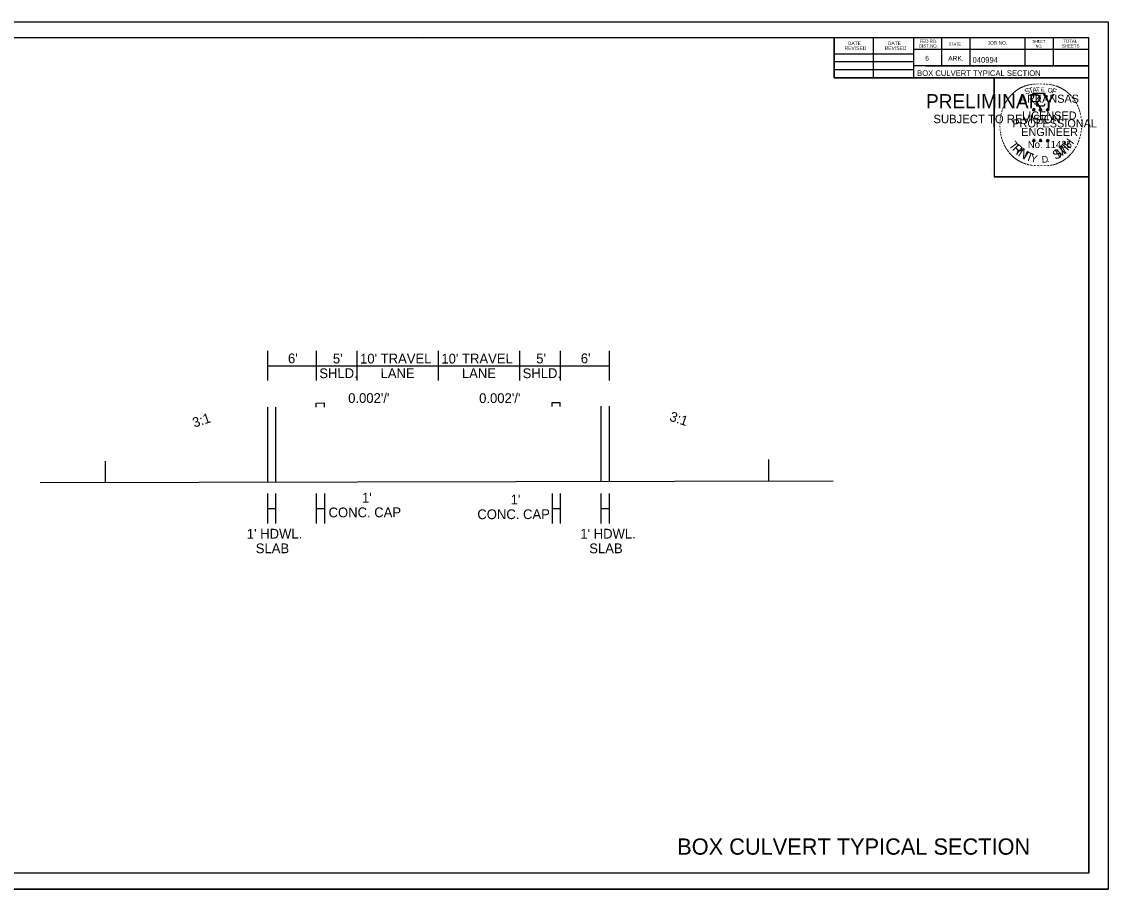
# Model space of a CAD drawing. Extents: x 1381471 to 1382703, y 370300 to 371487.
# Drawn here: x 1382383.6 to 1382517.2, y 370748.7 to 370855.4 of the extents above; entities that cross this region are included whole.
import ezdxf

# ---------------------------------------------------------------- set-up
doc = ezdxf.new("R2010")
doc.units = 0
for name, color, linetype in [('Default', 7, 'Continuous'), ('Level 15', 7, 'Continuous'), ('Level 16', 7, 'Continuous'), ('Level 21', 7, 'Continuous'), ('Level 26', 7, 'Continuous'), ('Level 39', 7, 'Continuous'), ('Level 6', 7, 'Continuous'), ('Level 8', 7, 'Continuous'), ('Level 9', 7, 'Continuous')]:
    doc.layers.add(name, color=color, linetype=linetype)

msp = doc.modelspace()

# ---------------------------------------------------------------- linework, layer by layer
at = {"layer": 'Default'}
for p, q in [((1382413.84, 370808.01), (1382413.84, 370798.75)), ((1382414.84, 370808.01), (1382414.84, 370798.75)), ((1382454.84, 370808.11), (1382454.84, 370798.85)), ((1382455.84, 370808.11), (1382455.84, 370798.85)), ((1382393.92, 370798.7), (1382393.92, 370801.37)), ((1382475.47, 370798.9), (1382475.47, 370801.56))]:
    msp.add_line(p, q, dxfattribs=at)
at = {"layer": 'Level 16'}
msp.add_line((1382483.39, 370798.91), (1382385.89, 370798.68), dxfattribs=at)
at = {"layer": 'Level 26'}
for p, q in [((1382350.55, 370855.4), (1382517.22, 370855.4)), ((1382502.86, 370837.28), (1382502.86, 370837.28)), ((1382350.55, 370748.73), (1382517.22, 370748.73))]:
    msp.add_line(p, q, dxfattribs=at)
for points in [[(1382350.55, 370855.4), (1382517.22, 370855.4), (1382517.22, 370748.73), (1382350.55, 370748.73)], [(1382473.71, 370853.45), (1382483.52, 370853.45), (1382483.52, 370848.51), (1382491.58, 370848.51), (1382503.17, 370848.51), (1382503.17, 370836.34), (1382514.84, 370836.34), (1382514.84, 370750.72), (1382356.75, 370750.72), (1382356.75, 370853.45)], [(1382503.17, 370848.51), (1382514.78, 370848.51), (1382514.84, 370836.34), (1382503.24, 370836.34)]]:
    msp.add_lwpolyline(points, close=True, dxfattribs=at)
at = {"layer": 'Level 39'}
for p, q in [((1382419.84, 370808.01), (1382419.84, 370808.51)), ((1382420.84, 370808.02), (1382420.84, 370808.52)), ((1382448.84, 370808.08), (1382448.84, 370808.58)), ((1382449.84, 370808.08), (1382449.84, 370808.58))]:
    msp.add_line(p, q, dxfattribs=at)
at = {"layer": 'Level 6'}
for p, q in [((1382356.75, 370853.45), (1382514.84, 370853.45)), ((1382433.01, 370853.32), (1382433.01, 370853.32)), ((1382433.01, 370853.32), (1382433.01, 370853.32)), ((1382483.52, 370848.51), (1382483.52, 370853.45)), ((1382488.36, 370848.51), (1382488.36, 370853.45)), ((1382493.29, 370853.45), (1382493.29, 370848.51)), ((1382496.71, 370853.45), (1382496.71, 370849.98)), ((1382500.18, 370853.45), (1382500.18, 370849.98)), ((1382506.97, 370853.45), (1382506.97, 370849.98)), ((1382510.44, 370853.45), (1382510.44, 370849.98)), ((1382514.84, 370750.72), (1382514.84, 370853.45)), ((1382514.84, 370851.98), (1382493.29, 370851.98)), ((1382514.84, 370851.99), (1382514.84, 370851.99)), ((1382483.52, 370851.44), (1382493.29, 370851.44)), ((1382483.52, 370850.51), (1382493.29, 370850.51)), ((1382483.52, 370849.54), (1382493.29, 370849.54)), ((1382514.84, 370849.98), (1382493.29, 370849.98)), ((1382494.77, 370849.98), (1382514.84, 370849.98)), ((1382514.84, 370848.51), (1382483.52, 370848.51)), ((1382413.84, 370814.91), (1382413.84, 370811.27)), ((1382419.84, 370814.91), (1382419.84, 370811.27)), ((1382424.84, 370814.91), (1382424.84, 370811.27)), ((1382434.84, 370814.91), (1382434.84, 370811.27)), ((1382444.84, 370814.91), (1382444.84, 370811.27)), ((1382449.84, 370814.91), (1382449.84, 370811.27)), ((1382455.84, 370814.91), (1382455.84, 370811.27)), ((1382413.84, 370813.09), (1382455.84, 370813.09)), ((1382419.84, 370808.51), (1382420.84, 370808.52)), ((1382448.84, 370808.58), (1382449.84, 370808.58)), ((1382413.84, 370797.37), (1382413.84, 370793.72)), ((1382414.84, 370797.37), (1382414.84, 370793.72)), ((1382419.84, 370797.37), (1382419.84, 370793.72)), ((1382420.84, 370797.37), (1382420.84, 370793.72)), ((1382448.84, 370797.37), (1382448.84, 370793.72)), ((1382449.84, 370797.37), (1382449.84, 370793.72)), ((1382454.84, 370797.37), (1382454.84, 370793.72)), ((1382455.84, 370797.37), (1382455.84, 370793.72)), ((1382413.84, 370795.54), (1382414.84, 370795.54)), ((1382419.84, 370795.54), (1382420.84, 370795.54)), ((1382448.84, 370795.54), (1382449.84, 370795.54)), ((1382454.84, 370795.54), (1382455.84, 370795.54)), ((1382514.84, 370750.72), (1382356.75, 370750.72))]:
    msp.add_line(p, q, dxfattribs=at)
at = {"layer": 'Level 8'}
for p, q in [((1382507.88, 370844.64), (1382508.06, 370844.58)), ((1382507.88, 370844.64), (1382508.01, 370844.61)), ((1382507.88, 370844.64), (1382508, 370844.57)), ((1382507.95, 370844.43), (1382508.06, 370844.58)), ((1382507.95, 370844.43), (1382508.01, 370844.55)), ((1382507.95, 370844.43), (1382508.06, 370844.54)), ((1382508.06, 370844.76), (1382508.04, 370844.64)), ((1382508.06, 370844.58), (1382508.06, 370844.76)), ((1382508.06, 370844.76), (1382508.08, 370844.64)), ((1382508.23, 370844.64), (1382508.06, 370844.58)), ((1382508.16, 370844.43), (1382508.06, 370844.58)), ((1382508.16, 370844.43), (1382508.06, 370844.54)), ((1382508.23, 370844.64), (1382508.09, 370844.61)), ((1382508.16, 370844.43), (1382508.09, 370844.58)), ((1382508.23, 370844.64), (1382508.13, 370844.58)), ((1382508.72, 370844.64), (1382508.89, 370844.58)), ((1382508.72, 370844.64), (1382508.84, 370844.61)), ((1382508.72, 370844.64), (1382508.84, 370844.57)), ((1382508.78, 370844.43), (1382508.89, 370844.58)), ((1382508.78, 370844.43), (1382508.85, 370844.55)), ((1382508.78, 370844.43), (1382508.89, 370844.54)), ((1382508.89, 370844.76), (1382508.87, 370844.64)), ((1382508.89, 370844.58), (1382508.89, 370844.76)), ((1382508.89, 370844.76), (1382508.92, 370844.64)), ((1382509.06, 370844.64), (1382508.89, 370844.58)), ((1382509, 370844.43), (1382508.89, 370844.58)), ((1382509, 370844.43), (1382508.89, 370844.54)), ((1382509.06, 370844.64), (1382508.92, 370844.61)), ((1382509, 370844.43), (1382508.93, 370844.58)), ((1382509.06, 370844.64), (1382508.96, 370844.58)), ((1382509.6, 370844.63), (1382509.77, 370844.57)), ((1382509.6, 370844.63), (1382509.73, 370844.61)), ((1382509.6, 370844.63), (1382509.72, 370844.57)), ((1382509.67, 370844.43), (1382509.77, 370844.57)), ((1382509.67, 370844.43), (1382509.73, 370844.55)), ((1382509.67, 370844.43), (1382509.77, 370844.53)), ((1382509.77, 370844.76), (1382509.75, 370844.63)), ((1382509.77, 370844.57), (1382509.77, 370844.76)), ((1382509.77, 370844.76), (1382509.8, 370844.63)), ((1382509.95, 370844.63), (1382509.77, 370844.57)), ((1382509.88, 370844.43), (1382509.77, 370844.57)), ((1382509.88, 370844.43), (1382509.77, 370844.53)), ((1382509.95, 370844.63), (1382509.8, 370844.6)), ((1382509.88, 370844.43), (1382509.81, 370844.57)), ((1382509.95, 370844.63), (1382509.84, 370844.58)), ((1382507.88, 370840.85), (1382508.05, 370840.79)), ((1382507.88, 370840.85), (1382508.01, 370840.83)), ((1382507.88, 370840.85), (1382508, 370840.79)), ((1382507.95, 370840.64), (1382508.05, 370840.79)), ((1382507.95, 370840.64), (1382508.01, 370840.77)), ((1382507.95, 370840.64), (1382508.05, 370840.75)), ((1382508.05, 370840.98), (1382508.03, 370840.85)), ((1382508.05, 370840.79), (1382508.05, 370840.98)), ((1382508.05, 370840.98), (1382508.08, 370840.85)), ((1382508.23, 370840.85), (1382508.05, 370840.79)), ((1382508.16, 370840.64), (1382508.05, 370840.79)), ((1382508.16, 370840.64), (1382508.05, 370840.75)), ((1382508.23, 370840.85), (1382508.08, 370840.82)), ((1382508.16, 370840.64), (1382508.09, 370840.79)), ((1382508.23, 370840.85), (1382508.13, 370840.8)), ((1382508.71, 370840.85), (1382508.89, 370840.79)), ((1382508.71, 370840.85), (1382508.84, 370840.83)), ((1382508.71, 370840.85), (1382508.83, 370840.79)), ((1382508.78, 370840.64), (1382508.89, 370840.79)), ((1382508.78, 370840.64), (1382508.84, 370840.77)), ((1382508.78, 370840.64), (1382508.89, 370840.75)), ((1382508.89, 370840.98), (1382508.87, 370840.85)), ((1382508.89, 370840.79), (1382508.89, 370840.98)), ((1382508.89, 370840.98), (1382508.91, 370840.85)), ((1382509.06, 370840.85), (1382508.89, 370840.79)), ((1382509, 370840.64), (1382508.89, 370840.79)), ((1382509, 370840.64), (1382508.89, 370840.75)), ((1382509.06, 370840.85), (1382508.92, 370840.82)), ((1382509, 370840.64), (1382508.93, 370840.79)), ((1382509.06, 370840.85), (1382508.96, 370840.8)), ((1382509.6, 370840.84), (1382509.77, 370840.79)), ((1382509.6, 370840.84), (1382509.72, 370840.82)), ((1382509.6, 370840.84), (1382509.72, 370840.78)), ((1382509.66, 370840.64), (1382509.77, 370840.79)), ((1382509.66, 370840.64), (1382509.73, 370840.76)), ((1382509.66, 370840.64), (1382509.77, 370840.75)), ((1382509.77, 370840.97), (1382509.75, 370840.84)), ((1382509.77, 370840.79), (1382509.77, 370840.97)), ((1382509.77, 370840.97), (1382509.8, 370840.85)), ((1382509.95, 370840.84), (1382509.77, 370840.79)), ((1382509.88, 370840.64), (1382509.77, 370840.79)), ((1382509.88, 370840.64), (1382509.77, 370840.75)), ((1382509.95, 370840.84), (1382509.8, 370840.82)), ((1382509.88, 370840.64), (1382509.81, 370840.79)), ((1382509.95, 370840.84), (1382509.84, 370840.79))]:
    msp.add_line(p, q, dxfattribs=at)
for points in [[(1382507.9, 370846.57), (1382508.04, 370846.16)], [(1382509.66, 370846.11), (1382509.73, 370846.26), (1382509.39, 370846.24), (1382509.46, 370846.57), (1382507.9, 370846.57)], [(1382508.15, 370845.36), (1382508.15, 370845.32), (1382508.43, 370845.31), (1382508.4, 370845.07), (1382509.34, 370845.07), (1382509.44, 370845.34)], [(1382508.06, 370844.76), (1382508.16, 370844.43), (1382507.88, 370844.64), (1382508.23, 370844.64), (1382507.95, 370844.43), (1382508.06, 370844.76)], [(1382508.89, 370844.76), (1382509, 370844.43), (1382508.72, 370844.64), (1382509.06, 370844.64), (1382508.78, 370844.43), (1382508.89, 370844.76)], [(1382509.77, 370844.76), (1382509.88, 370844.43), (1382509.6, 370844.63), (1382509.95, 370844.63), (1382509.67, 370844.43), (1382509.77, 370844.76)], [(1382508.05, 370840.98), (1382508.16, 370840.64), (1382507.88, 370840.85), (1382508.23, 370840.85), (1382507.95, 370840.64), (1382508.05, 370840.98)], [(1382508.89, 370840.98), (1382509, 370840.64), (1382508.71, 370840.85), (1382509.06, 370840.85), (1382508.78, 370840.64), (1382508.89, 370840.98)], [(1382509.77, 370840.97), (1382509.88, 370840.64), (1382509.6, 370840.84), (1382509.95, 370840.84), (1382509.66, 370840.64), (1382509.77, 370840.97)]]:
    msp.add_lwpolyline(points, dxfattribs=at)
for centre, radius in [((1382508.06, 370844.58), 0.0861), ((1382508.06, 370844.58), 0.0723), ((1382508.06, 370844.58), 0.0579), ((1382508.06, 370844.58), 0.0495), ((1382508.06, 370844.58), 0.0374), ((1382508.06, 370844.58), 0.0248), ((1382508.06, 370844.58), 0.0148), ((1382508.89, 370844.58), 0.0861), ((1382508.89, 370844.58), 0.0723), ((1382508.89, 370844.58), 0.0579), ((1382508.89, 370844.58), 0.0495), ((1382508.89, 370844.58), 0.0374), ((1382508.89, 370844.58), 0.0248), ((1382508.89, 370844.58), 0.0148), ((1382509.77, 370844.57), 0.0861), ((1382509.77, 370844.57), 0.0723), ((1382509.77, 370844.57), 0.0579), ((1382509.77, 370844.57), 0.0495), ((1382509.77, 370844.57), 0.0374), ((1382509.77, 370844.57), 0.0248), ((1382509.77, 370844.57), 0.0148), ((1382508.05, 370840.79), 0.0861), ((1382508.05, 370840.79), 0.0723), ((1382508.05, 370840.79), 0.0579), ((1382508.05, 370840.79), 0.0495), ((1382508.05, 370840.79), 0.0374), ((1382508.05, 370840.79), 0.0248), ((1382508.05, 370840.79), 0.0148), ((1382508.89, 370840.79), 0.0861), ((1382508.89, 370840.79), 0.0723), ((1382508.89, 370840.79), 0.0579), ((1382508.89, 370840.79), 0.0495), ((1382508.89, 370840.79), 0.0374), ((1382508.89, 370840.79), 0.0248), ((1382508.89, 370840.79), 0.0148), ((1382509.77, 370840.79), 0.0861), ((1382509.77, 370840.79), 0.0723), ((1382509.77, 370840.79), 0.0579), ((1382509.77, 370840.79), 0.0495), ((1382509.77, 370840.79), 0.0374), ((1382509.77, 370840.79), 0.0248), ((1382509.77, 370840.79), 0.0148)]:
    msp.add_circle(centre, radius, dxfattribs=at)

# ---------------------------------------------------------------- texts
at = {"layer": 'Level 15'}
msp.add_text('BOX CULVERT TYPICAL SECTION', height=2, dxfattribs=at).set_placement((1382464.22, 370752.98))
at = {"layer": 'Level 21'}
for s, rotation, p in [("6'", 0.1364, (1382416.37, 370813.4)), ("5'", 0.1364, (1382421.89, 370813.38)), ("10' TRAVEL ", 0.1364, (1382425.23, 370813.37)), ("10' TRAVEL ", 0.1364, (1382435.23, 370813.37)), ("5'", 0.1364, (1382446.89, 370813.38)), ("6'", 0.1364, (1382452.37, 370813.4)), ('SHLD.', 0.1364, (1382420.22, 370811.57)), ('LANE', 0.1364, (1382427.75, 370811.57)), ('LANE', 0.1364, (1382437.75, 370811.57)), ('SHLD.', 0.1364, (1382445.22, 370811.57)), ("0.002'/'", 0.1364, (1382423.77, 370808.52)), ("0.002'/'", 0.1365, (1382439.87, 370808.51)), ('3:1', 18.4349, (1382404.86, 370805.48)), ('3:1', 341.5651, (1382463.18, 370806.37)), ("1'", 0.1364, (1382425.46, 370796.27)), ("1'", 0.1364, (1382443.75, 370796.04)), ('CONC. CAP', 0.1364, (1382421.36, 370794.46)), ('CONC. CAP', 0.1364, (1382439.65, 370794.23)), ("1' HDWL.", 0.1364, (1382411.31, 370791.84)), ("1' HDWL.", 0.1364, (1382452.31, 370791.84)), ('SLAB', 0.1364, (1382412.41, 370790.04)), ('SLAB', 0.1364, (1382453.41, 370790.04))]:
    msp.add_text(s, height=1.2, rotation=rotation, dxfattribs=at).set_placement(p)
at = {"layer": 'Level 6'}
for s, height, p in [('REVISED', 0.44, (1382484.8, 370851.93)), ('DATE', 0.44, (1382485.19, 370852.52)), ('REVISED', 0.44, (1382489.73, 370851.93)), ('DATE', 0.44, (1382490.12, 370852.52)), ('DIST.NO.', 0.391, (1382493.93, 370852.22)), ('FED.RD.', 0.391, (1382494.03, 370852.81)), ('STATE', 0.342, (1382497.59, 370852.47)), ('JOB NO.', 0.44, (1382502.38, 370852.57)), ('SHEET', 0.342, (1382507.9, 370852.81)), ('NO.', 0.342, (1382508.29, 370852.22)), ('SHEETS', 0.391, (1382511.52, 370852.22)), ('TOTAL', 0.391, (1382511.66, 370852.81)), ('6', 0.586, (1382494.71, 370850.61)), ('ARK.', 0.586, (1382497.54, 370850.61)), ('040994', 0.7, (1382500.53, 370850.35)), ('BOX CULVERT TYPICAL SECTION', 0.7, (1382493.72, 370848.72))]:
    msp.add_text(s, height=height, rotation=360, dxfattribs=at).set_placement(p)
at = {"layer": 'Level 8'}
for s, height, rotation, p in [('-', 1.18, 42.9622, (1382505.6, 370846.06)), ('-', 1.19, 38.9507, (1382505.82, 370846.27)), ('-', 1.2, 36.2317, (1382506.05, 370846.46)), ('-', 1.2, 34.0636, (1382506.34, 370846.66)), ('-', 1.18, 28.7918, (1382506.64, 370846.84)), ('-', 1.15, 24.3072, (1382506.96, 370847)), ('S', 0.696, 21.594, (1382507.08, 370846.41)), ('-', 1.08, 19.1761, (1382507.28, 370847.14)), ('T', 0.645, 16.4036, (1382507.54, 370846.58)), ('-', 0.982, 13.6302, (1382507.65, 370847.26)), ('A', 0.585, 11.2132, (1382507.95, 370846.7)), ('-', 0.917, 10.2193, (1382507.99, 370847.34)), ('T', 0.529, 6.0228, (1382508.37, 370846.79)), ('-', 0.844, 5.8968, (1382508.35, 370847.39)), ('-', 0.8, 0.1862, (1382508.74, 370847.43)), ('E', 0.501, 0.8323, (1382508.93, 370846.84)), ('-', 0.807, 357.743, (1382509.1, 370847.42)), ('-', 0.874, 352.1617, (1382509.47, 370847.4)), ('O', 0.565, 350.4515, (1382509.73, 370846.74)), ('-', 0.966, 347.2049, (1382509.83, 370847.34)), ('F', 0.681, 340.0707, (1382510.21, 370846.62)), ('-', 1.05, 342.3362, (1382510.15, 370847.26)), ('-', 1.12, 337.8551, (1382510.52, 370847.15)), ('-', 1.16, 334.1211, (1382510.83, 370847.01)), ('-', 1.19, 329.6409, (1382511.12, 370846.87)), ('-', 1.2, 325.8627, (1382511.44, 370846.69)), ('-', 1.19, 320.5297, (1382511.75, 370846.48)), ('-', 1.17, 315.5786, (1382512.05, 370846.24)), ('-', 0.996, 62.8713, (1382504.65, 370844.73)), ('-', 1.05, 58.0706, (1382504.81, 370845.04)), ('-', 1.09, 54.2325, (1382504.97, 370845.3)), ('-', 1.12, 50.6142, (1382505.17, 370845.58)), ('-', 1.14, 48.423, (1382505.38, 370845.83)), ('ARKANSAS', 1, 360, (1382506.33, 370845.43)), ('-', 1.13, 309.8797, (1382512.33, 370845.96)), ('-', 1.1, 306.6522, (1382512.6, 370845.66)), ('-', 0.933, 303.6753, (1382512.84, 370845.38)), ('-', 1.02, 299.6684, (1382513, 370845.07)), ('-', 0.867, 75.461, (1382504.31, 370843.75)), ('-', 0.895, 72.3945, (1382504.41, 370844.11)), ('-', 0.942, 67.7743, (1382504.52, 370844.42)), ('LICENSED', 1, 360, (1382506.63, 370843.36)), ('DWB', 0.005, 360, (1382508.05, 370844.58)), ('DWB', 0.005, 360, (1382508.88, 370844.58)), ('DWB', 0.005, 360, (1382509.77, 370844.57)), ('-', 0.968, 294.6628, (1382513.16, 370844.77)), ('-', 0.925, 290.5728, (1382513.29, 370844.48)), ('-', 0.872, 285.1233, (1382513.41, 370844.19)), ('-', 0.806, 94.1959, (1382504.21, 370842.34)), ('-', 0.8, 89.0622, (1382504.2, 370842.7)), ('-', 0.808, 85.1863, (1382504.21, 370843.05)), ('-', 0.826, 81.2013, (1382504.25, 370843.39)), ('PROFESSIONAL', 1, 360, (1382505.42, 370842.4)), ('-', 0.837, 280.5493, (1382513.51, 370843.82)), ('-', 0.815, 276.5962, (1382513.59, 370843.43)), ('-', 0.806, 274.3301, (1382513.62, 370843.07)), ('-', 0.8, 269.9407, (1382513.63, 370842.76)), ('-', 0.827, 98.9479, (1382504.25, 370842)), ('-', 0.845, 101.7149, (1382504.32, 370841.64)), ('-', 0.875, 105.4578, (1382504.4, 370841.34)), ('-', 0.909, 109.0874, (1382504.5, 370841.02)), ('ENGINEER', 1, 360, (1382506.51, 370841.34)), ('-', 0.89, 252.8681, (1382513.44, 370841.4)), ('-', 0.864, 255.7626, (1382513.53, 370841.76)), ('-', 0.827, 260.9953, (1382513.59, 370842.1)), ('-', 0.814, 263.5172, (1382513.62, 370842.42)), ('-', 0.962, 114.0643, (1382504.63, 370840.73)), ('-', 0.98, 115.7289, (1382504.78, 370840.42)), ('-', 1.03, 120.4471, (1382504.96, 370840.12)), ('-', 1.09, 125.8934, (1382505.16, 370839.84)), ('T', 1.05, 306.0406, (1382504.93, 370840.21)), ('R', 1.12, 314.005, (1382505.32, 370839.69)), ('I', 1.15, 321.9694, (1382505.77, 370839.22)), ('N', 1.15, 326.5002, (1382506.05, 370838.99)), ('No. 11425', 0.878, 360, (1382507.32, 370839.87)), ('DWB', 0.005, 360, (1382508.05, 370840.79)), ('DWB', 0.005, 360, (1382508.88, 370840.79)), ('DWB', 0.005, 360, (1382509.77, 370840.79)), ('M', 1.15, 32.6563, (1382511.13, 370838.6)), ('I', 1.14, 42.1136, (1382511.77, 370839.02)), ('T', 1.11, 46.6444, (1382512.05, 370839.26)), ('H', 1.04, 54.6088, (1382512.49, 370839.73)), ('-', 1.04, 239.0712, (1382513, 370840.37)), ('-', 0.976, 244.6197, (1382513.2, 370840.75)), ('-', 0.941, 247.8887, (1382513.33, 370841.06)), ('-', 1.13, 130.7181, (1382505.4, 370839.57)), ('-', 1.16, 134.2238, (1382505.65, 370839.29)), ('-', 1.19, 138.9338, (1382505.92, 370839.06)), ('-', 1.2, 144.6463, (1382506.19, 370838.86)), ('-', 1.2, 148.0898, (1382506.47, 370838.67)), ('I', 1.11, 335.3603, (1382506.65, 370838.59)), ('T', 1.05, 339.8912, (1382506.98, 370838.43)), ('Y', 0.918, 347.8556, (1382507.59, 370838.21)), ('D', 0.82, 6.3969, (1382509.08, 370838.03)), ('S', 1.13, 26.9312, (1382510.71, 370838.39)), ('-', 1.2, 215.7363, (1382511.81, 370838.99)), ('-', 1.19, 221.0851, (1382512.09, 370839.22)), ('-', 1.16, 225.7653, (1382512.35, 370839.48)), ('-', 1.12, 231.2538, (1382512.59, 370839.76)), ('-', 1.09, 233.8452, (1382512.8, 370840.04)), ('-', 1.18, 151.5704, (1382506.76, 370838.51)), ('-', 1.16, 154.6002, (1382507.03, 370838.39)), ('-', 1.11, 158.5612, (1382507.34, 370838.26)), ('-', 1.05, 162.7983, (1382507.68, 370838.15)), ('-', 0.959, 167.5555, (1382508.04, 370838.07)), ('-', 0.859, 173.1155, (1382508.42, 370838.02)), ('-', 0.816, 176.5183, (1382508.8, 370837.99)), ('-', 0.803, 181.5918, (1382509.17, 370838)), ('-', 0.843, 185.8167, (1382509.57, 370838.04)), ('-', 0.937, 191.2858, (1382509.94, 370838.1)), ('.', 0.947, 13.7642, (1382509.68, 370838.09)), ('-', 1.02, 195.4743, (1382510.31, 370838.2)), ('-', 1.1, 200.7184, (1382510.65, 370838.32)), ('-', 1.14, 204.2516, (1382510.96, 370838.46)), ('-', 1.17, 207.3568, (1382511.27, 370838.62)), ('-', 1.2, 212.2491, (1382511.55, 370838.79))]:
    msp.add_text(s, height=height, rotation=rotation, dxfattribs=at).set_placement(p)
at = {"layer": 'Level 9'}
for s, height, p in [('PRELIMINARY', 1.75, (1382494.81, 370844.74)), ('DWB', 0.005, (1382495.19, 370845.66)), ('SUBJECT TO REVISION', 1.0376, (1382495.72, 370842.92))]:
    msp.add_text(s, height=height, rotation=360, dxfattribs=at).set_placement(p)

doc.saveas('drawing.dxf')
